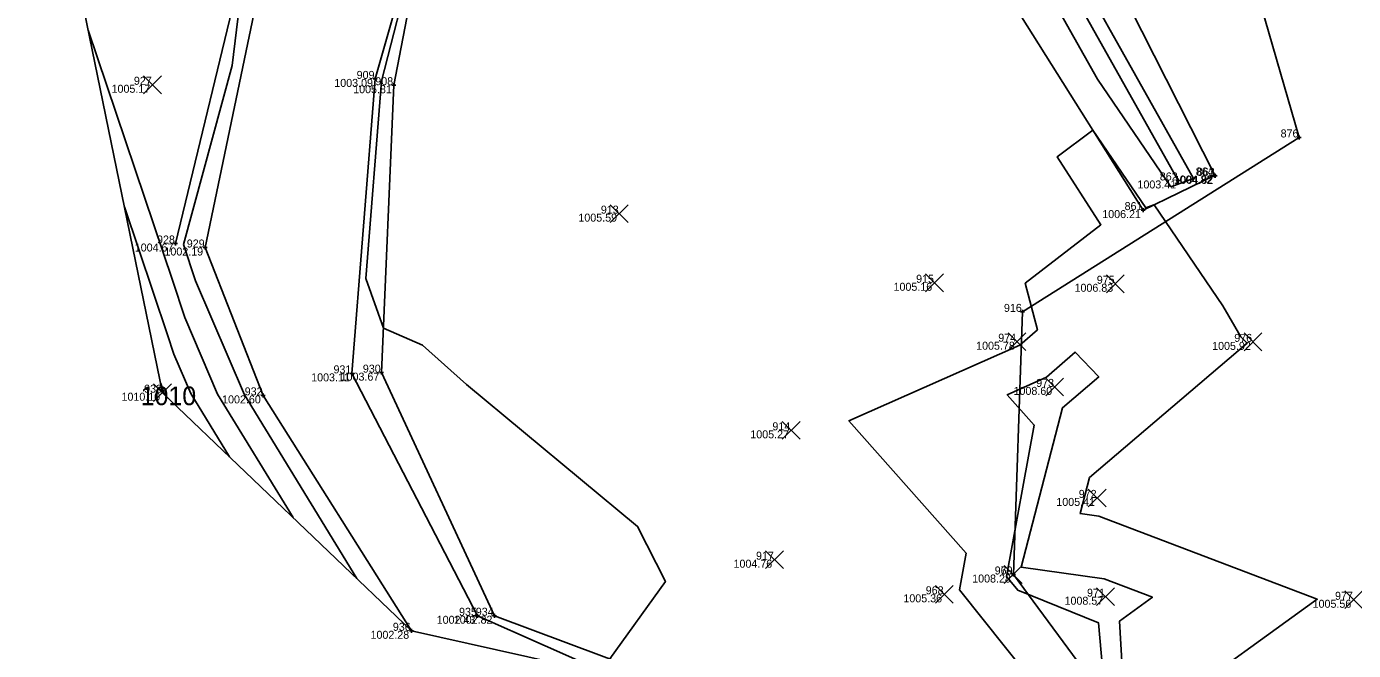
# Model space of a CAD drawing. Extents: x 2354693 to 2355622, y 637071 to 710080.
# Drawn here: x 2355058.5 to 2355257.5, y 709322.8 to 709416.4 of the extents above; entities that cross this region are included whole.
import ezdxf

# ---------------------------------------------------------------- set-up
doc = ezdxf.new("R2010")
doc.units = 0
for name, color, linetype in [('Default', 7, 'Continuous'), ('DR_X_Ditch', 7, 'Continuous'), ('DT_X_Contour_Major', 7, 'Continuous'), ('DT_X_Contour_Minor', 7, 'Continuous'), ('HY_X_Water_Edge', 7, 'Continuous'), ('SV_X_Random_Point', 7, 'Continuous'), ('SV_X_Shot_Marker', 7, 'Continuous'), ('SV_X_Text_Elevation', 7, 'Continuous'), ('SV_X_Text_Name', 7, 'Continuous'), ('SV_X_Toe_of_Slope', 7, 'Continuous'), ('SV_X_Top_of_Bank', 7, 'Continuous'), ('VG_X_Tree_Line_Rt', 7, 'Continuous')]:
    doc.layers.add(name, color=color, linetype=linetype)

msp = doc.modelspace()

# ---------------------------------------------------------------- linework, layer by layer
at = {"layer": 'Default'}
msp.add_lwpolyline([(2355192.85, 709575.71), (2355160.05, 709542.81), (2355116.76, 709509.42), (2355081.06, 709480.43), (2355058.46, 709461.11), (2355065.45, 709426.86), (2355078.86, 709361.48), (2355116.19, 709325.77), (2355146.4, 709319.01), (2355178.16, 709243.86), (2355227.43, 709181.3), (2355213.36, 709127.54), (2355205.69, 709069.16), (2355203.89, 709062.28), (2355168.12, 708973.83)], dxfattribs=at)
msp.add_lwpolyline([(2355192.85, 709575.71), (2355160.05, 709542.81), (2355116.76, 709509.42), (2355081.06, 709480.43), (2355058.46, 709461.11), (2355065.45, 709426.86), (2355078.86, 709361.48), (2355116.19, 709325.77), (2355146.4, 709319.01), (2355178.16, 709243.86), (2355227.43, 709181.3), (2355213.36, 709127.54), (2355205.69, 709069.16), (2355203.89, 709062.28), (2355168.12, 708973.83)], dxfattribs=at)
at = {"layer": 'DR_X_Ditch'}
msp.add_lwpolyline([(2355124.33, 709514.48), (2355146.96, 709489.42), (2355158.35, 709485.61), (2355171.76, 709484.06), (2355201.09, 709446.92), (2355231.21, 709393.32)], dxfattribs=at)
at = {"layer": 'DT_X_Contour_Major'}
msp.add_lwpolyline([(2355079.35, 709361.01), (2355079.07, 709361.47), (2355078.94, 709361.76), (2355078.89, 709361.91), (2355078.58, 709362.85)], dxfattribs=at)
msp.add_lwpolyline([(2355079.35, 709361.01), (2355079.07, 709361.47), (2355078.94, 709361.76), (2355078.89, 709361.91), (2355078.58, 709362.85)], dxfattribs=at)
at = {"layer": 'DT_X_Contour_Minor'}
for points in [[(2355158.48, 709494), (2355174.2, 709486.45), (2355189.39, 709468.18), (2355203.29, 709448.68), (2355216.21, 709424.49), (2355216.18, 709424.48), (2355233.49, 709393.63), (2355230.1, 709392.38), (2355219.1, 709408.53), (2355198.44, 709445.19), (2355181.49, 709464.42), (2355168.68, 709481.23), (2355160.69, 709482.54), (2355156.13, 709481.67), (2355147.07, 709489.38), (2355156.99, 709493.95), (2355158.48, 709494)], [(2355158.48, 709494), (2355174.2, 709486.45), (2355189.39, 709468.18), (2355203.29, 709448.68), (2355216.21, 709424.49), (2355216.18, 709424.48), (2355233.49, 709393.63), (2355230.1, 709392.38), (2355219.1, 709408.53), (2355198.44, 709445.19), (2355181.49, 709464.42), (2355168.68, 709481.23), (2355160.69, 709482.54), (2355156.13, 709481.67), (2355147.07, 709489.38), (2355156.99, 709493.95), (2355158.48, 709494)], [(2355091.27, 709426.68), (2355089.28, 709410.54), (2355082.02, 709383.7), (2355083.8, 709378.28), (2355091.14, 709361.15), (2355108, 709333.61)], [(2355091.27, 709426.68), (2355089.28, 709410.54), (2355082.02, 709383.7), (2355083.8, 709378.28), (2355091.14, 709361.15), (2355108, 709333.61)], [(2355145.94, 709321.55), (2355154.28, 709333.16), (2355150.1, 709341.43), (2355124.44, 709362.7), (2355117.86, 709368.61), (2355112, 709371.18), (2355109.35, 709378.62), (2355111.69, 709408.23), (2355116.34, 709426.38)], [(2355145.94, 709321.55), (2355154.28, 709333.16), (2355150.1, 709341.43), (2355124.44, 709362.7), (2355117.86, 709368.61), (2355112, 709371.18), (2355109.35, 709378.62), (2355111.69, 709408.23), (2355116.34, 709426.38)], [(2355098.45, 709342.74), (2355087.12, 709361.26), (2355082.18, 709372.77), (2355080.34, 709378.37), (2355067.7, 709415.85)], [(2355098.45, 709342.74), (2355087.12, 709361.26), (2355082.18, 709372.77), (2355080.34, 709378.37), (2355067.7, 709415.85)], [(2355226.33, 709389.21), (2355218.4, 709400.85), (2355213.03, 709396.86), (2355219.61, 709386.67), (2355208.27, 709377.89), (2355210.08, 709370.93), (2355207.47, 709368.6), (2355181.81, 709357.27), (2355199.4, 709337.4), (2355198.39, 709331.9), (2355212.18, 709314.63)], [(2355226.33, 709389.21), (2355218.4, 709400.85), (2355213.03, 709396.86), (2355219.61, 709386.67), (2355208.27, 709377.89), (2355210.08, 709370.93), (2355207.47, 709368.6), (2355181.81, 709357.27), (2355199.4, 709337.4), (2355198.39, 709331.9), (2355212.18, 709314.63)], [(2355088.9, 709351.87), (2355083.09, 709361.37), (2355080.56, 709367.27), (2355079.62, 709370.14), (2355073.14, 709389.35)], [(2355088.9, 709351.87), (2355083.09, 709361.37), (2355080.56, 709367.27), (2355079.62, 709370.14), (2355073.14, 709389.35)], [(2355229.78, 709314.4), (2355252.05, 709330.49), (2355219.28, 709342.95), (2355216.47, 709343.35), (2355217.87, 709348.76), (2355241.52, 709368.9), (2355240.6, 709369.87), (2355237.9, 709374.51), (2355227.58, 709389.66), (2355227.56, 709389.66), (2355226.33, 709389.21)], [(2355229.78, 709314.4), (2355252.05, 709330.49), (2355219.28, 709342.95), (2355216.47, 709343.35), (2355217.87, 709348.76), (2355241.52, 709368.9), (2355240.6, 709369.87), (2355237.9, 709374.51), (2355227.58, 709389.66), (2355227.56, 709389.66), (2355226.33, 709389.21)], [(2355223.4, 709309.98), (2355222.4, 709327.22), (2355227.34, 709330.79), (2355220.07, 709333.56), (2355207.66, 709335.32), (2355213.86, 709359.23), (2355219.29, 709363.85), (2355215.74, 709367.58), (2355211.47, 709363.79), (2355205.57, 709361.18), (2355209.61, 709356.62), (2355205.47, 709333.93), (2355207.14, 709331.84), (2355219.24, 709326.97), (2355220.73, 709310.09), (2355227.94, 709295.41), (2355223.4, 709309.98)], [(2355223.4, 709309.98), (2355222.4, 709327.22), (2355227.34, 709330.79), (2355220.07, 709333.56), (2355207.66, 709335.32), (2355213.86, 709359.23), (2355219.29, 709363.85), (2355215.74, 709367.58), (2355211.47, 709363.79), (2355205.57, 709361.18), (2355209.61, 709356.62), (2355205.47, 709333.93), (2355207.14, 709331.84), (2355219.24, 709326.97), (2355220.73, 709310.09), (2355227.94, 709295.41), (2355223.4, 709309.98)]]:
    msp.add_lwpolyline(points, dxfattribs=at)
at = {"layer": 'HY_X_Water_Edge'}
msp.add_lwpolyline([(2355099.14, 709490.23), (2355112.83, 709450.59), (2355116.9, 709430.14), (2355110.74, 709408.55), (2355107.27, 709364.38), (2355126.09, 709328.02), (2355146.4, 709319.01), (2355178.16, 709243.86), (2355207.27, 709238.41), (2355228.23, 709233.04), (2355237.12, 709206.89), (2355247.9, 709203.67), (2355256.61, 709243.12), (2355267.3, 709285.53), (2355279.14, 709298.91), (2355298.35, 709321.78), (2355310.42, 709328.49), (2355317.24, 709340.56)], dxfattribs=at)
at = {"layer": 'SV_X_Random_Point'}
for p, q in [((2355076.01, 709406.33), (2355078.68, 709409)), ((2355076.01, 709409), (2355078.68, 709406.33)), ((2355146.02, 709387.01), (2355148.69, 709389.68)), ((2355146.02, 709389.68), (2355148.69, 709387.01)), ((2355193.32, 709376.63), (2355195.99, 709379.3)), ((2355193.32, 709379.3), (2355195.99, 709376.63)), ((2355220.42, 709376.48), (2355223.09, 709379.15)), ((2355220.42, 709379.15), (2355223.09, 709376.48)), ((2355205.7, 709367.79), (2355208.36, 709370.46)), ((2355205.7, 709370.46), (2355208.36, 709367.79)), ((2355241.08, 709367.77), (2355243.74, 709370.44)), ((2355241.08, 709370.44), (2355243.74, 709367.77)), ((2355211.33, 709361.01), (2355213.99, 709363.68)), ((2355211.33, 709363.68), (2355213.99, 709361.01)), ((2355077.52, 709360.14), (2355080.19, 709362.81)), ((2355077.52, 709362.81), (2355080.19, 709360.14)), ((2355171.82, 709354.5), (2355174.49, 709357.17)), ((2355171.82, 709357.17), (2355174.49, 709354.5)), ((2355217.71, 709344.36), (2355220.38, 709347.03)), ((2355217.71, 709347.03), (2355220.38, 709344.36)), ((2355169.32, 709335.09), (2355171.99, 709337.76)), ((2355169.32, 709337.76), (2355171.99, 709335.09)), ((2355205.12, 709332.88), (2355207.78, 709335.55)), ((2355205.12, 709335.55), (2355207.78, 709332.88)), ((2355194.79, 709329.91), (2355197.46, 709332.58)), ((2355194.79, 709332.58), (2355197.46, 709329.91)), ((2355218.96, 709329.54), (2355221.63, 709332.21)), ((2355218.96, 709332.21), (2355221.63, 709329.54)), ((2355256.17, 709329.09), (2355258.84, 709331.76)), ((2355256.17, 709331.76), (2355258.84, 709329.09))]:
    msp.add_line(p, q, dxfattribs=at)
at = {"layer": 'SV_X_Shot_Marker'}
for p, q in [((2355111.04, 709408.55), (2355110.44, 709408.55)), ((2355110.74, 709408.85), (2355110.74, 709408.25)), ((2355113.87, 709407.6), (2355113.27, 709407.6)), ((2355113.57, 709407.9), (2355113.57, 709407.3)), ((2355249.66, 709399.77), (2355249.06, 709399.77)), ((2355249.36, 709400.07), (2355249.36, 709399.47)), ((2355231.51, 709393.32), (2355230.91, 709393.32)), ((2355231.21, 709393.62), (2355231.21, 709393.02)), ((2355236.95, 709394.06), (2355236.35, 709394.06)), ((2355237.05, 709394.01), (2355236.45, 709394.01)), ((2355236.65, 709394.36), (2355236.65, 709393.76)), ((2355236.75, 709394.31), (2355236.75, 709393.71)), ((2355226.23, 709388.87), (2355225.63, 709388.87)), ((2355225.93, 709389.17), (2355225.93, 709388.57)), ((2355081.12, 709383.86), (2355080.52, 709383.86)), ((2355080.82, 709384.16), (2355080.82, 709383.56)), ((2355085.57, 709383.26), (2355084.97, 709383.26)), ((2355085.27, 709383.56), (2355085.27, 709382.96)), ((2355208.16, 709373.6), (2355207.56, 709373.6)), ((2355207.86, 709373.9), (2355207.86, 709373.3)), ((2355107.57, 709364.38), (2355106.97, 709364.38)), ((2355107.27, 709364.68), (2355107.27, 709364.08)), ((2355112.01, 709364.49), (2355111.41, 709364.49)), ((2355111.71, 709364.79), (2355111.71, 709364.19)), ((2355093.95, 709361.38), (2355093.95, 709360.78)), ((2355094.25, 709361.08), (2355093.65, 709361.08)), ((2355206.78, 709334.22), (2355206.18, 709334.22)), ((2355206.48, 709334.52), (2355206.48, 709333.92)), ((2355126.39, 709328.02), (2355125.79, 709328.02)), ((2355126.09, 709328.32), (2355126.09, 709327.72)), ((2355128.96, 709328.03), (2355128.36, 709328.03)), ((2355128.66, 709328.33), (2355128.66, 709327.73)), ((2355116.49, 709325.77), (2355115.89, 709325.77)), ((2355116.19, 709326.07), (2355116.19, 709325.47))]:
    msp.add_line(p, q, dxfattribs=at)
at = {"layer": 'SV_X_Toe_of_Slope'}
for points in [[(2355099.14, 709490.23), (2355112.83, 709450.59), (2355116.9, 709430.14), (2355110.74, 709408.55), (2355107.27, 709364.38), (2355126.09, 709328.02), (2355146.4, 709319.01), (2355178.16, 709243.86), (2355207.27, 709238.41), (2355228.23, 709233.04), (2355237.12, 709206.89), (2355247.9, 709203.67), (2355256.61, 709243.12), (2355267.3, 709285.53), (2355279.14, 709298.91), (2355298.35, 709321.78), (2355310.42, 709328.49), (2355317.24, 709340.56)], [(2355083.52, 709479.26), (2355089.1, 709442.93), (2355094.03, 709425.51), (2355085.27, 709383.26), (2355093.95, 709361.08), (2355116.19, 709325.77)]]:
    msp.add_lwpolyline(points, dxfattribs=at)
at = {"layer": 'SV_X_Top_of_Bank'}
for points in [[(2355130.76, 709519.1), (2355156.77, 709495.29), (2355177.83, 709490.02), (2355207.39, 709451.95), (2355236.75, 709394.01)], [(2355116.76, 709509.42), (2355137.58, 709484.99), (2355151.24, 709472.97), (2355164.56, 709477.47), (2355192.83, 709441.52), (2355225.93, 709388.87), (2355236.65, 709394.06)], [(2355100.08, 709490.73), (2355115.52, 709450.05), (2355117.98, 709430.72), (2355113.57, 709407.6), (2355111.71, 709364.49), (2355128.66, 709328.03), (2355150.44, 709319.86), (2355166.79, 709277.66), (2355166, 709276.87), (2355178.56, 709246.01), (2355206.83, 709240.61), (2355229.16, 709234.35), (2355238.05, 709208.04), (2355245.62, 709205.75), (2355249.4, 709246.95), (2355254.61, 709273.36), (2355264.37, 709286.54), (2355255.26, 709298.36), (2355265.16, 709308.45), (2355274.57, 709302.63), (2355292.81, 709328.24), (2355310.42, 709346), (2355315.95, 709345.13)], [(2355081.06, 709480.43), (2355086.64, 709443.04), (2355091.15, 709426.72), (2355080.82, 709383.86)]]:
    msp.add_lwpolyline(points, dxfattribs=at)
at = {"layer": 'VG_X_Tree_Line_Rt'}
msp.add_lwpolyline([(2355286.87, 709031.33), (2355312.43, 709075.83), (2355322.75, 709120.09), (2355304.91, 709171.78), (2355297.85, 709210.36), (2355206.48, 709334.22), (2355207.86, 709373.6), (2355249.36, 709399.77), (2355239.7, 709433.16), (2355219.43, 709459.42), (2355185.29, 709497.16), (2355152.29, 709534.91)], dxfattribs=at)

# ---------------------------------------------------------------- texts
at = {"layer": 'DT_X_Contour_Major'}
msp.add_text('1010', height=2.8, dxfattribs=at).set_placement((2355075.57, 709359.61))
msp.add_text('1010', height=2.8, dxfattribs=at).set_placement((2355075.57, 709359.61))
at = {"layer": 'SV_X_Text_Elevation'}
for s, p in [('1005.17', (2355071.21, 709406.47)), ('1003.09', (2355104.62, 709407.35)), ('1005.81', (2355107.45, 709406.4)), ('1003.41', (2355225.09, 709392.12)), ('1004.82', (2355230.53, 709392.86)), ('1004.82', (2355230.63, 709392.81)), ('1005.59', (2355141.23, 709387.14)), ('1006.21', (2355219.81, 709387.67)), ('1004.67', (2355074.69, 709382.66)), ('1002.19', (2355079.14, 709382.06)), ('1005.16', (2355188.5, 709376.77)), ('1006.83', (2355215.65, 709376.62)), ('1005.78', (2355200.89, 709367.93)), ('1005.92', (2355236.29, 709367.9)), ('1003.11', (2355101.15, 709363.18)), ('1003.67', (2355105.57, 709363.29)), ('1010.10', (2355072.7, 709360.28)), ('1008.60', (2355206.5, 709361.15)), ('1002.60', (2355087.79, 709359.88)), ('1005.27', (2355167.02, 709354.64)), ('1005.41', (2355212.92, 709344.5)), ('1004.76', (2355164.5, 709335.23)), ('1008.28', (2355200.3, 709333.01)), ('1005.36', (2355189.98, 709330.04)), ('1008.57', (2355214.15, 709329.68)), ('1005.56', (2355251.36, 709329.22)), ('1002.43', (2355119.98, 709326.82)), ('1002.82', (2355122.54, 709326.83)), ('1002.28', (2355110.05, 709324.57))]:
    msp.add_text(s, height=1.2, dxfattribs=at).set_placement(p)
at = {"layer": 'SV_X_Text_Name'}
for s, p in [('909', (2355107.97, 709408.55)), ('927', (2355074.56, 709407.67)), ('908', (2355110.77, 709407.6)), ('876', (2355246.56, 709399.77)), ('864', (2355233.83, 709394.06)), ('863', (2355233.99, 709394.01)), ('862', (2355228.44, 709393.32)), ('913', (2355144.6, 709388.34)), ('861', (2355223.16, 709388.87)), ('928', (2355078.03, 709383.86)), ('929', (2355082.49, 709383.26)), ('915', (2355191.89, 709377.97)), ('975', (2355218.99, 709377.82)), ('916', (2355205.06, 709373.6)), ('974', (2355204.21, 709369.13)), ('976', (2355239.61, 709369.1)), ('931', (2355104.5, 709364.38)), ('930', (2355108.9, 709364.49)), ('973', (2355209.9, 709362.35)), ('933', (2355076.1, 709361.48)), ('932', (2355091.18, 709361.08)), ('914', (2355170.33, 709355.84)), ('972', (2355216.28, 709345.7)), ('917', (2355167.87, 709336.43)), ('970', (2355203.68, 709334.22)), ('969', (2355203.67, 709334.21)), ('968', (2355193.33, 709331.24)), ('971', (2355217.52, 709330.88)), ('977', (2355254.72, 709330.42)), ('935', (2355123.33, 709328.02)), ('934', (2355125.84, 709328.03)), ('936', (2355113.4, 709325.77))]:
    msp.add_text(s, height=1.2, dxfattribs=at).set_placement(p)

doc.saveas('drawing.dxf')
